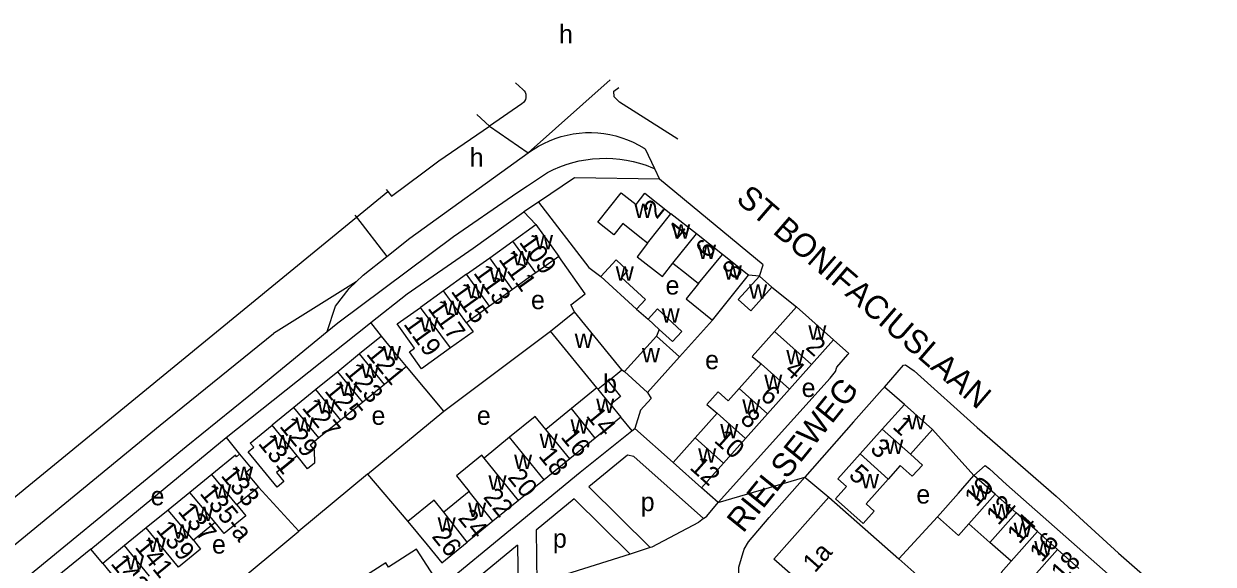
# Model space of a CAD drawing. Extents: x 161258 to 163262, y 380749 to 382054.
# Drawn here: x 162678.1 to 162932.8, y 381937.9 to 382053.6 of the extents above; entities that cross this region are included whole.
import ezdxf

# ---------------------------------------------------------------- set-up
doc = ezdxf.new("R2010")
doc.units = 0
for name, color, linetype in [('BLT_Basislijn', 7, 'Continuous'), ('BLT_Bebouwing', 7, 'Continuous'), ('BLT_Centroide', 7, 'Continuous'), ('BLT_Huisnummer', 7, 'Continuous'), ('BLT_Huisnummer_ tussenligend', 7, 'Continuous'), ('BLT_Huisnummer_reeks', 7, 'Continuous'), ('BLT_Onderverdeling_panden', 7, 'Continuous'), ('BLT_Straatnaam', 7, 'Continuous'), ('BLT_Vlakafsluiter', 7, 'Continuous')]:
    doc.layers.add(name, color=color, linetype=linetype)

msp = doc.modelspace()

# ---------------------------------------------------------------- linework, layer by layer
at = {"layer": 'BLT_Basislijn'}
for p, q in [((162783.37, 382040.94), (162784.97, 382039.55)), ((162804.5, 382037.96), (162804.41, 382039.14)), ((162784.75, 382036.43), (162777.81, 382031.69)), ((162775.13, 382034.14), (162777.81, 382031.69)), ((162811.17, 382026.78), (162813.16, 382022.57)), ((162785.96, 382018.88), (162790.26, 382021.73)), ((162813.16, 382022.57), (162814.23, 382020.29)), ((162755.71, 382018.09), (162756.03, 382017.7)), ((162784.54, 382017.95), (162785.96, 382018.88)), ((162749.33, 382012.2), (162756.03, 382017.7)), ((162756.03, 382017.7), (162756.85, 382016.67)), ((162782.75, 382016.72), (162784.54, 382017.95)), ((162788.33, 382015.38), (162785.15, 382013.34)), ((162787.76, 382010.6), (162785.15, 382013.34)), ((162694.53, 381967.27), (162749.33, 382012.2)), ((162835.6, 381999.58), (162833.26, 381999.77)), ((162838.27, 381997.19), (162843.52, 381992.99)), ((162818.51, 381982.27), (162825.55, 381990.14)), ((162726.29, 381973.95), (162743.07, 381987.68)), ((162743.07, 381987.68), (162745.35, 381989.54)), ((162754.71, 381986.73), (162752.39, 381989.6)), ((162768.06, 381970.66), (162790.9, 381987.75)), ((162814.13, 381988.16), (162813.55, 381986.73)), ((162707.32, 381967.63), (162731.55, 381987.28)), ((162854.78, 381982.97), (162851.47, 381985.89)), ((162768.06, 381970.66), (162760.05, 381980.17)), ((162806.18, 381979.5), (162806.7, 381979.11)), ((162861.9, 381975.26), (162862.36, 381975.79)), ((162866.64, 381972.1), (162862.36, 381975.79)), ((162653.02, 381923.11), (162707.32, 381967.63)), ((162663.14, 381941.64), (162694.53, 381967.27)), ((162805.94, 381969.27), (162808.29, 381966.45)), ((162692.45, 381941.12), (162721.46, 381965.01)), ((162721.46, 381965.01), (162724.33, 381961.4)), ((162808.29, 381966.45), (162808.92, 381966.95)), ((162808.92, 381966.95), (162817.11, 381959.65)), ((162881.54, 381956.86), (162872.66, 381966.72)), ((162751.73, 381957.14), (162737.03, 381944.95)), ((162751.73, 381957.14), (162760.37, 381947.02)), ((162799.07, 381954.42), (162812.23, 381941.41)), ((162845.33, 381956.52), (162850.47, 381952.23)), ((162737.03, 381944.95), (162728.36, 381954.33)), ((162795.96, 381951.87), (162787.79, 381945.18)), ((162795.96, 381951.87), (162807.92, 381940.04)), ((162826.77, 381951.08), (162823.18, 381954.22)), ((162865.45, 381939.02), (162873.72, 381948.04)), ((162708.68, 381921.45), (162737.03, 381944.95)), ((162787.79, 381945.18), (162787.93, 381933.7)), ((162783.83, 381941.93), (162783.94, 381932.43)), ((162692.45, 381941.12), (162629.3, 381889.6)), ((162695.02, 381938.03), (162692.45, 381941.12)), ((162807.92, 381940.04), (162787.93, 381933.7)), ((162812.23, 381941.41), (162807.92, 381940.04))]:
    msp.add_line(p, q, dxfattribs=at)
for points in [[(162784.97, 382039.55), (162785.24, 382039.26), (162785.44, 382038.93), (162785.58, 382038.55), (162785.63, 382038.16), (162785.61, 382037.77), (162785.51, 382037.38), (162785.33, 382037.03), (162785.09, 382036.72), (162784.75, 382036.43)], [(162804.41, 382039.14), (162805.52, 382039.92)], [(162818.16, 382028.91), (162805.67, 382036.79), (162804.5, 382037.96)], [(162756.85, 382016.67), (162763.52, 382021.67), (162766.98, 382024.24), (162777.81, 382031.69)], [(162786.07, 382025.95), (162787.19, 382026.66), (162788.31, 382027.36), (162789.47, 382027.99), (162790.67, 382028.55), (162791.89, 382029.03), (162793.15, 382029.44), (162794.43, 382029.77), (162795.72, 382030.03), (162797.03, 382030.2), (162798.35, 382030.3), (162799.67, 382030.32), (162800.99, 382030.25), (162802.3, 382030.11), (162803.6, 382029.88), (162804.89, 382029.58), (162806.15, 382029.2), (162807.39, 382028.75), (162808.6, 382028.22), (162809.78, 382027.62), (162810.91, 382026.95), (162811.17, 382026.78)], [(162755.86, 382003.79), (162760.75, 382007.67), (162786.07, 382025.95)], [(162790.26, 382021.73), (162791.56, 382022.38), (162792.9, 382022.95), (162794.26, 382023.45), (162795.64, 382023.87), (162797.05, 382024.21), (162798.48, 382024.48), (162799.91, 382024.66), (162801.36, 382024.77), (162802.81, 382024.8), (162804.26, 382024.74), (162805.7, 382024.61), (162807.14, 382024.4), (162808.56, 382024.11), (162809.96, 382023.74), (162811.34, 382023.29), (162812.69, 382022.77), (162813.16, 382022.57)], [(162814.23, 382020.29), (162796.03, 382020.63), (162788.33, 382015.38)], [(162835.6, 381999.58), (162836.4, 382001.99), (162814.23, 382020.29)], [(162745.35, 381989.54), (162770.12, 382008.03), (162782.75, 382016.72)], [(162752.39, 381989.6), (162760.2, 381995.74), (162774.3, 382005.52), (162785.15, 382013.34)], [(162788.33, 382015.38), (162799.12, 382001.43), (162801.65, 381999.46)], [(162749.27, 381998.34), (162750.75, 381999.73), (162755.86, 382003.79)], [(162795.99, 381991.93), (162795.26, 381993.43), (162798.34, 381995.79), (162792.65, 382003.77)], [(162743.07, 381987.68), (162744.89, 381993.15), (162747.78, 381996.94), (162749.27, 381998.34)], [(162809.29, 381992.45), (162811.76, 381990.33)], [(162721.46, 381965.01), (162751.96, 381989.26), (162752.39, 381989.6)], [(162826.77, 381951.08), (162850.72, 381977.7), (162851.87, 381979.1), (162852.19, 381980.03), (162854.57, 381982.74), (162854.78, 381982.97)], [(162862.36, 381975.79), (162866.48, 381980.5), (162866.89, 381980.58), (162868.74, 381979.29), (162882.2, 381967.11), (162899.17, 381952.42), (162912.51, 381940.2), (162940.62, 381915.6), (162943.78, 381912.25), (162944.33, 381910.1), (162944.21, 381907.91), (162943.46, 381906.19), (162931.99, 381893.02), (162930.91, 381891.53), (162923.61, 381883.02), (162918.82, 381877.66), (162917.08, 381873.75)], [(162861.9, 381975.26), (162855.75, 381968.32), (162845.33, 381956.52)], [(162670.33, 381928.23), (162712.86, 381963.04), (162726.29, 381973.95)], [(162811.65, 381974.65), (162812.41, 381973.32), (162810.18, 381970.82), (162808.92, 381966.95)], [(162751.73, 381957.14), (162767.64, 381970.31), (162768.06, 381970.66)], [(162767.4, 381933.03), (162797.23, 381957.59), (162808.29, 381966.45)], [(162823.66, 381947.64), (162808.72, 381960.96), (162807.35, 381961.21), (162799.07, 381954.42)], [(162881.54, 381956.86), (162883.92, 381958.99), (162884.88, 381958.3), (162888.51, 381954.9), (162924.15, 381923.46), (162923.21, 381921.86), (162922.25, 381920.79)], [(162843.13, 381901.85), (162831.68, 381931.25), (162831.17, 381934.48), (162831.17, 381937.24), (162832.32, 381941.07), (162833.27, 381942.66), (162837.69, 381947.88), (162845.33, 381956.52)], [(162823.66, 381947.64), (162824.35, 381948.16), (162826.77, 381951.08)], [(162823.66, 381947.64), (162822.54, 381946.78), (162812.61, 381941.53), (162812.23, 381941.41)], [(162783.83, 381941.93), (162772.82, 381932.9), (162774.3, 381929.1)]]:
    msp.add_lwpolyline(points, dxfattribs=at)
at = {"layer": 'BLT_Bebouwing'}
for p, q in [((162822.11, 382008.6), (162816.65, 382012.93)), ((162782.82, 382007.05), (162787.76, 382010.6)), ((162787.76, 382010.6), (162792.65, 382003.77)), ((162827.72, 382004.16), (162822.11, 382008.6)), ((162777.87, 382003.5), (162782.82, 382007.05)), ((162772.93, 381999.95), (162777.87, 382003.5)), ((162792.65, 382003.77), (162787.71, 382000.23)), ((162772.93, 381999.95), (162767.98, 381996.41)), ((162809.29, 381992.45), (162801.65, 381999.46)), ((162838.27, 381997.19), (162835.6, 381999.58)), ((162767.98, 381996.41), (162763.03, 381992.86)), ((162782.76, 381996.68), (162777.82, 381993.13)), ((162777.82, 381993.13), (162772.87, 381989.58)), ((162843.52, 381992.99), (162838.81, 381987.71)), ((162851.47, 381985.89), (162843.52, 381992.99)), ((162790.9, 381987.75), (162795.99, 381991.93)), ((162806.18, 381979.5), (162795.99, 381991.93)), ((162814.13, 381988.16), (162811.76, 381990.33)), ((162800.83, 381975.64), (162790.9, 381987.75)), ((162754.71, 381986.73), (162750.02, 381982.91)), ((162806.7, 381979.11), (162813.55, 381986.73)), ((162818.51, 381982.27), (162813.55, 381986.73)), ((162846.76, 381980.62), (162851.47, 381985.89)), ((162750.02, 381982.91), (162745.34, 381979.09)), ((162760.05, 381980.17), (162755.37, 381976.36)), ((162811.65, 381974.65), (162818.51, 381982.27)), ((162835.96, 381980.77), (162831.25, 381975.49)), ((162842.04, 381975.34), (162846.76, 381980.62)), ((162745.34, 381979.09), (162740.65, 381975.27)), ((162803.2, 381977.05), (162806.18, 381979.5)), ((162811.65, 381974.65), (162806.7, 381979.11)), ((162740.65, 381975.27), (162735.96, 381971.45)), ((162755.37, 381976.36), (162750.68, 381972.54)), ((162800.83, 381975.64), (162795.35, 381971.18)), ((162800.83, 381975.64), (162801.08, 381975.33)), ((162837.33, 381970.06), (162842.04, 381975.34)), ((162750.68, 381972.54), (162745.99, 381968.72)), ((162735.96, 381971.45), (162731.28, 381967.63)), ((162795.35, 381971.18), (162789.87, 381966.72)), ((162803.74, 381972.06), (162805.95, 381969.32)), ((162826.53, 381970.21), (162821.82, 381964.93)), ((162832.61, 381964.78), (162837.33, 381970.06)), ((162861.9, 381966.79), (162866.64, 381972.1)), ((162866.64, 381972.1), (162872.66, 381966.72)), ((162745.99, 381968.72), (162741.31, 381964.9)), ((162805.95, 381969.32), (162800.48, 381964.87)), ((162782.12, 381965.05), (162776.65, 381960.59)), ((162800.48, 381964.87), (162795, 381960.41)), ((162821.82, 381964.93), (162817.11, 381959.65)), ((162827.9, 381959.5), (162832.61, 381964.78)), ((162857.16, 381961.48), (162861.9, 381966.79)), ((162795, 381960.41), (162789.52, 381955.96)), ((162817.11, 381959.65), (162823.18, 381954.22)), ((162823.18, 381954.22), (162827.9, 381959.5)), ((162718.36, 381957.05), (162713.7, 381953.25)), ((162789.52, 381955.96), (162784.04, 381951.5)), ((162886.06, 381952.85), (162881.54, 381956.86)), ((162713.7, 381953.25), (162709.03, 381949.44)), ((162728.36, 381954.33), (162723.74, 381950.57)), ((162773.5, 381953.41), (162768.07, 381948.99)), ((162850.47, 381952.23), (162865.45, 381939.02)), ((162890.58, 381948.84), (162886.06, 381952.85)), ((162709.03, 381949.44), (162704.36, 381945.64)), ((162784.04, 381951.5), (162778.56, 381947.05)), ((162719.09, 381946.78), (162714.44, 381942.99)), ((162778.56, 381947.05), (162773.08, 381942.59)), ((162895.11, 381944.84), (162890.58, 381948.84)), ((162704.36, 381945.64), (162699.69, 381941.84)), ((162884.96, 381942.49), (162880.44, 381946.5)), ((162899.43, 381941.01), (162895.11, 381944.84)), ((162699.69, 381941.84), (162695.02, 381938.03)), ((162889.48, 381938.49), (162884.96, 381942.49)), ((162903.98, 381936.97), (162899.43, 381941.01)), ((162865.45, 381939.02), (162875.33, 381930.25))]:
    msp.add_line(p, q, dxfattribs=at)
for points in [[(162811.65, 382006.61), (162810.03, 382007.89), (162806.36, 382010.79), (162804.46, 382008.39), (162801.03, 382011.11), (162806.01, 382017.4), (162809.19, 382014.88), (162811.11, 382017.31), (162816.65, 382012.93)], [(162811.65, 382006.61), (162809.43, 382003.68), (162814.84, 381999.49), (162817.04, 382002.33)], [(162801.65, 381999.46), (162804.91, 382003.01), (162807.39, 382000.73), (162806.06, 381999.28), (162811.22, 381994.55), (162809.29, 381992.45)], [(162833.26, 381999.77), (162832.97, 382000), (162827.72, 382004.16)], [(162787.71, 382000.23), (162787.42, 382000.02), (162782.76, 381996.68)], [(162817.04, 382002.33), (162819.97, 382000.02), (162822.57, 381997.96)], [(162822.57, 381997.96), (162819.93, 381994.71), (162825.55, 381990.14)], [(162825.55, 381990.14), (162830.15, 381995.85), (162833.26, 381999.77)], [(162835.6, 381999.58), (162831.08, 381994.52), (162833.75, 381992.13), (162838.27, 381997.19)], [(162769.48, 381984.17), (162763.29, 381979.73), (162760.69, 381983.36), (162761.79, 381984.15), (162758.09, 381989.31), (162763.03, 381992.86)], [(162811.76, 381990.33), (162813.79, 381992.54), (162819.03, 381987.73), (162817.01, 381985.53), (162814.13, 381988.16)], [(162772.87, 381989.58), (162774.35, 381987.66), (162769.48, 381984.17)], [(162838.81, 381987.71), (162834.04, 381982.36), (162835.96, 381980.77)], [(162760.05, 381980.17), (162758.62, 381981.92), (162757.87, 381982.85), (162754.71, 381986.73)], [(162803.2, 381977.05), (162805.86, 381973.79), (162803.74, 381972.06)], [(162831.25, 381975.49), (162828.92, 381972.88), (162826.79, 381974.78), (162824.38, 381972.06), (162826.53, 381970.21)], [(162736.62, 381961.08), (162732.2, 381957.48), (162733.78, 381955.55), (162732.34, 381954.38), (162726.17, 381961.95), (162727.34, 381962.9), (162726.59, 381963.82), (162731.28, 381967.63)], [(162789.87, 381966.72), (162787.6, 381969.5), (162782.12, 381965.05)], [(162741.31, 381964.9), (162739.41, 381963.35), (162740.29, 381962.27), (162740.37, 381959.49), (162738.89, 381958.29), (162736.62, 381961.08)], [(162872.66, 381966.72), (162869.67, 381963.36), (162867.92, 381961.41)], [(162724.33, 381961.4), (162723.69, 381960.89), (162723.44, 381961.19), (162718.36, 381957.05)], [(162724.33, 381961.4), (162726.78, 381958.4), (162725.73, 381957.54), (162728.36, 381954.33)], [(162776.65, 381960.59), (162776.18, 381961.21), (162770.75, 381956.8), (162773.5, 381953.41)], [(162863.18, 381956.1), (162858.45, 381950.79), (162860.19, 381949.23), (162857.83, 381946.58), (162851.89, 381951.88), (162854.26, 381954.53), (162852.42, 381956.17), (162857.16, 381961.48)], [(162867.92, 381961.41), (162870.54, 381959.11), (162868.34, 381956.7), (162865.77, 381959), (162863.18, 381956.1)], [(162873.72, 381948.04), (162878.22, 381953.11), (162881.54, 381956.86)], [(162854.23, 381927.9), (162852.18, 381928.98), (162850.11, 381929.91), (162848.02, 381930.72), (162838.68, 381938.94), (162850.47, 381952.23)], [(162723.74, 381950.57), (162725.64, 381948.24), (162721.01, 381944.43), (162720.64, 381944.88), (162719.09, 381946.78)], [(162768.07, 381948.99), (162765.97, 381951.58), (162760.37, 381947.02)], [(162760.37, 381947.02), (162764.45, 381942.01), (162767.6, 381938.13), (162773.08, 381942.59)], [(162880.44, 381946.5), (162878.25, 381944.02), (162873.72, 381948.04)], [(162714.44, 381942.99), (162715.99, 381941.09), (162711.23, 381937.21)], [(162767.4, 381933.03), (162762.23, 381941.12), (162756.18, 381937.26)], [(162695.02, 381938.03), (162698.18, 381934.16), (162700.34, 381931.5)], [(162756.18, 381937.26), (162755.61, 381938.15), (162749.7, 381934.39), (162750.65, 381932.91)], [(162893.81, 381934.66), (162891.67, 381932.24), (162887.33, 381936.08), (162889.48, 381938.49)]]:
    msp.add_lwpolyline(points, dxfattribs=at)
at = {"layer": 'BLT_Onderverdeling_panden'}
for p, q in [((162811.65, 382006.61), (162816.65, 382012.93)), ((162817.04, 382002.33), (162822.11, 382008.6)), ((162787.71, 382000.23), (162782.82, 382007.05)), ((162782.76, 381996.68), (162777.87, 382003.5)), ((162822.57, 381997.96), (162827.72, 382004.16)), ((162777.82, 381993.13), (162772.93, 381999.95)), ((162772.87, 381989.58), (162767.98, 381996.41)), ((162769.48, 381984.17), (162763.03, 381992.86)), ((162846.76, 381980.62), (162838.81, 381987.71)), ((162755.37, 381976.36), (162750.02, 381982.91)), ((162842.04, 381975.34), (162835.96, 381980.77)), ((162750.68, 381972.54), (162745.34, 381979.09)), ((162745.99, 381968.72), (162740.65, 381975.27)), ((162803.74, 381972.06), (162801.08, 381975.33)), ((162837.33, 381970.06), (162831.25, 381975.49)), ((162741.31, 381964.9), (162735.96, 381971.45)), ((162800.48, 381964.87), (162795.35, 381971.18)), ((162832.61, 381964.78), (162826.53, 381970.21)), ((162736.62, 381961.08), (162731.28, 381967.63)), ((162789.52, 381955.96), (162782.12, 381965.05)), ((162795, 381960.41), (162789.87, 381966.72)), ((162827.9, 381959.5), (162821.82, 381964.93)), ((162867.92, 381961.41), (162861.9, 381966.79)), ((162784.04, 381951.5), (162776.65, 381960.59)), ((162863.18, 381956.1), (162857.16, 381961.48)), ((162723.74, 381950.57), (162718.36, 381957.05)), ((162719.09, 381946.78), (162713.7, 381953.25)), ((162778.56, 381947.05), (162773.5, 381953.41)), ((162880.44, 381946.5), (162886.06, 381952.85)), ((162714.44, 381942.99), (162709.03, 381949.44)), ((162773.08, 381942.59), (162768.07, 381948.99)), ((162884.96, 381942.49), (162890.58, 381948.84)), ((162711.23, 381937.21), (162704.36, 381945.64)), ((162889.48, 381938.49), (162895.11, 381944.84)), ((162705.01, 381935.3), (162699.69, 381941.84)), ((162893.81, 381934.66), (162899.43, 381941.01))]:
    msp.add_line(p, q, dxfattribs=at)
msp.add_lwpolyline([(162803.2, 381977.05), (162801.08, 381975.33)], dxfattribs=at)
at = {"layer": 'BLT_Vlakafsluiter'}
for p, q in [((162803.63, 382041.57), (162786.07, 382025.95)), ((162777.81, 382031.69), (162786.07, 382025.95)), ((162749.03, 382012.58), (162749.33, 382012.2)), ((162749.33, 382012.2), (162755.86, 382003.79)), ((162749.27, 381998.34), (162731.55, 381987.28)), ((162826.77, 381951.08), (162845.33, 381956.52))]:
    msp.add_line(p, q, dxfattribs=at)

# ---------------------------------------------------------------- texts
at = {"layer": 'BLT_Centroide'}
for s, p in [('h', (162792.71, 382049.38)), ('h', (162773.59, 382022.97)), ('w', (162808.83, 382012)), ('w', (162816.92, 382007.58)), ('w', (162787.56, 382005.3)), ('w', (162822.45, 382003.2)), ('w', (162782.8, 382001.86)), ('w', (162777.84, 381998.31)), ('w', (162804.85, 381998.55)), ('w', (162827.98, 381998.8)), ('w', (162772.91, 381994.77)), ('e', (162815.52, 381995.61)), ('w', (162833.39, 381994.7)), ('e', (162786.71, 381992.48)), ('w', (162767.95, 381991.22)), ('w', (162814.68, 381989.59)), ('w', (162763, 381987.67)), ('w', (162846.08, 381985.97)), ('w', (162796.07, 381984.17)), ('w', (162755.03, 381981.53)), ('w', (162810.46, 381981.12)), ('e', (162823.98, 381979.63)), ('w', (162841.36, 381980.69)), ('w', (162750.36, 381977.72)), ('b', (162802.14, 381974.56)), ('w', (162836.64, 381975.41)), ('w', (162745.67, 381973.91)), ('e', (162844.65, 381973.68)), ('w', (162740.98, 381970.09)), ('w', (162800.66, 381970.25)), ('w', (162831.94, 381970.12)), ('e', (162752.57, 381967.72)), ('e', (162775.12, 381967.72)), ('w', (162867.28, 381966.75)), ('w', (162736.3, 381966.27)), ('w', (162795.17, 381965.8)), ('w', (162827.22, 381964.84)), ('w', (162731.61, 381962.44)), ('w', (162788.56, 381962.72)), ('w', (162822.5, 381959.59)), ('w', (162862.54, 381961.44)), ('w', (162783.08, 381958.28)), ('w', (162723.36, 381955.7)), ('w', (162777.61, 381953.81)), ('w', (162857.36, 381954.14)), ('w', (162718.69, 381951.89)), ('w', (162880.98, 381951.69)), ('e', (162705.27, 381950.48)), ('p', (162810.2, 381949.23)), ('e', (162869.21, 381950.85)), ('w', (162714.8, 381947.14)), ('w', (162773.25, 381947.97)), ('w', (162885.52, 381947.67)), ('w', (162766.73, 381944.81)), ('w', (162890.03, 381943.66)), ('w', (162710.12, 381943.33)), ('p', (162791.4, 381941.4)), ('w', (162704.69, 381940.48)), ('e', (162718.42, 381940.14)), ('w', (162894.45, 381939.75)), ('w', (162700.02, 381936.67))]:
    msp.add_text(s, height=4, dxfattribs=at).set_placement(p)
at = {"layer": 'BLT_Huisnummer'}
for s, rotation, p in [('2', 51.6265, (162813.64, 382011.58)), ('109', 305.6535, (162784.02, 382006.82)), ('8', 51.63, (162830.45, 381998.6)), ('113', 305.6495, (162774.26, 382000.23)), ('119', 305.6482, (162759.3, 381989.27)), ('2', 318.2286, (162845.29, 381984.08)), ('121', 309.1774, (162751.3, 381982.84)), ('125', 309.1774, (162742.36, 381974.95)), ('6', 318.2281, (162835.55, 381973.6)), ('14', 309.1253, (162798.33, 381969.59)), ('1', 318.2469, (162863.91, 381967.09)), ('131', 309.1806, (162728.14, 381963.7)), ('18', 309.1253, (162788.16, 381960.99)), ('12', 318.2322, (162820.49, 381958.36)), ('133', 309.177, (162720.17, 381956.79)), ('5', 318.2469, (162854.52, 381956.67)), ('10', 48.4613, (162882.1, 381949.94)), ('22', 309.1253, (162776.34, 381952.19)), ('137', 309.1727, (162710.95, 381949.14)), ('14', 48.4619, (162891.23, 381942.02)), ('26', 309.1311, (162765.32, 381943.75)), ('143', 309.1506, (162696.59, 381937.96)), ('18', 48.4624, (162900.62, 381933.97))]:
    msp.add_text(s, height=4, rotation=rotation, dxfattribs=at).set_placement(p)
at = {"layer": 'BLT_Huisnummer_ tussenligend'}
for s, rotation, p in [('4', 51.6265, (162818.76, 382006.81)), ('6', 51.6265, (162824.71, 382003.1)), ('111', 305.6535, (162779.64, 382003.15)), ('115', 305.6495, (162769.44, 381996.29)), ('117', 305.6495, (162764.47, 381992.65)), ('123', 309.1774, (162746.64, 381978.95)), ('4', 318.2286, (162840.82, 381979.11)), ('127', 309.1774, (162737.53, 381971.31)), ('8', 318.2281, (162831.27, 381968.62)), ('129', 309.1774, (162732.72, 381967.36)), ('16', 309.1253, (162792.93, 381965.06)), ('10', 318.2281, (162825.72, 381964.15)), ('3', 318.2469, (162859.11, 381962.24)), ('20', 309.1253, (162781.55, 381956.4)), ('12', 48.4613, (162886.74, 381946.01)), ('24', 309.1253, (162770.93, 381947.67)), ('139', 309.1727, (162706.28, 381945.19)), ('16', 48.4619, (162896.03, 381938.08)), ('141', 309.1727, (162701.75, 381941.48))]:
    msp.add_text(s, height=4, rotation=rotation, dxfattribs=at).set_placement(p)
at = {"layer": 'BLT_Huisnummer_reeks'}
for s, rotation, p in [('135-a', 309.177, (162715.64, 381952.99)), ('1a', 48.3969, (162847.48, 381935.86))]:
    msp.add_text(s, height=4, rotation=rotation, dxfattribs=at).set_placement(p)
at = {"layer": 'BLT_Straatnaam'}
for s, height, rotation, p in [('ST BONIFACIUSLAAN', 4.9999, 319.2576, (162830.37, 382015.68)), ('RIELSEWEG', 5, 50.9844, (162832.12, 381944.35))]:
    msp.add_text(s, height=height, rotation=rotation, dxfattribs=at).set_placement(p)

doc.saveas('drawing.dxf')
